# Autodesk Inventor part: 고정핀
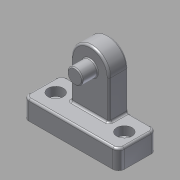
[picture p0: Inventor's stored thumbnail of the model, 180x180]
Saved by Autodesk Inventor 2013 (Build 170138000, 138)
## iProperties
Created: 2017-07
Part Number: 고정핀
Material: 알루미늄 6061
Document SubType Name: Modeling
Designer: mduedu
Density: 2.71 g/cm^3
Mass: 41.2292 g
Surface Area: 53.4313 cm^2
Volume: 15.2137 cm^3
Author: mduedu
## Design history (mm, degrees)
sketch "스케치1"
  geometry: L1 (-25, 0)-(25, 0); L2 (-25, 10)-(25, 10); L3 (-25, 0)-(-25, 10); L4 (25, 0)-(25, 10); L5 (-10, 10)-(10, 10); L6 (10, 10)-(10, 40); L7 (10, 40)-(-10, 40); L8 (-10, 40)-(-10, 10); 3 further points
  constraints: 16 end point, 4 parallel, 2 horizontal, 2 midpoint, 2 perpendicular, 1 coincident, 1 point on line, 1 vertical alignment
  dimensions: "d0" = 50 distance of L1.start L1.end; "d2" = 10 distance of L1.end L2.end; "d3" = 20 distance of L6.end L7.end; "d4" = 40 distance between parallel lines of L7 L1
extrude "돌출1" new body sketch "스케치1" stored distance "d5" = 20; taper "d6" = 0 deg
extrude "돌출2" join sketch "스케치1" distance "d7" = 10; taper "d8" = 0 deg
fillet "모깎기1"
sketch "스케치2"
  geometry: C1 r 4 at (0, 30); A1 r 10 centre (0, 30) between (10, 30) and (-10, 30) reference; 1 further point
  constraints: 1 centre point, 1 coincident
  dimensions: "d9" = 8 diameter of C1
extrude "돌출3" join sketch "스케치2" distance "d10" = 8; taper "d11" = 0 deg
fillet "모깎기2" dims "d12" = 0.5
fillet "모깎기3" dims "d13" = 1
fillet "모깎기4" dims "d14" = 1
fillet "모깎기5" dims "d15" = 3
fillet "모깎기6" dims "d16" = 1
chamfer "모따기1" distance "d18" = 0.5; stored, may be unused: second distance "d19" = 2, angle "d20" = 45 deg
sketch "스케치3"
  geometry: L1 (-16, 8)-(-16, -6) reference; L2 (34, -6)-(34, 8) reference; L3 (-16, 1)-(34, 1); L4 (-13, -9)-(31, -9) reference; L5 (9, 1)-(9, -9); 2 further points
  constraints: 4 end point, 3 midpoint, 1 point on line, 1 symmetric about line
  dimensions: "d21" = 7 distance from line of point (-9, 1) L1
sketch "스케치4"
  geometry: L1 (-16, 1)-(34, 1) reference; L2 (9, 1)-(9, -9) reference; 7 further points
  constraints: 2 coincident
hole "구멍1" sketch "스케치4" at (27, 1), (-9, 1) diameter "d22" = 4.5; stored, may be unused: countersink angle "d26" = 90 deg, drill point angle "d28" = 0 deg; dims "d23" = 6, "d24" = 8, "d25" = 4.6, "d27" = 8
node "솔리드1"
